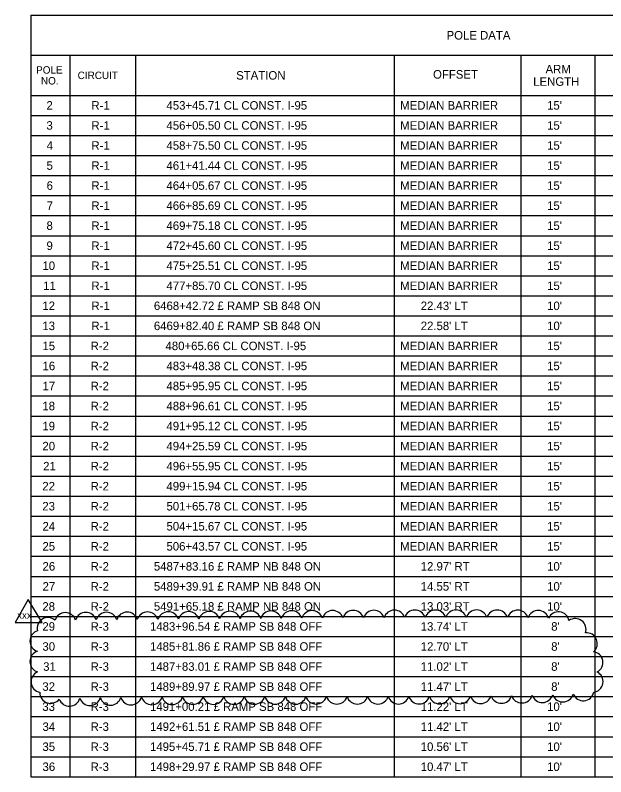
# Model space of a CAD drawing. Extents: x -816.7 to -800.7, y -2197.9 to -2187.9.
# Drawn here: x -816.09 to -811.23, y -2194.13 to -2187.86 of the extents above; entities that cross this region are included whole.
import ezdxf

# ---------------------------------------------------------------- set-up
doc = ezdxf.new("R2010")
doc.units = 0
for name, color, linetype in [('ScratchEle_dp', 7, 'Continuous'), ('SumBoxBorder_dp', 7, 'Continuous'), ('SumBoxLines_dp', 7, 'Continuous'), ('SumBoxLinesMin_dp', 7, 'Continuous'), ('TextLabel', 7, 'Continuous')]:
    doc.layers.add(name, color=color, linetype=linetype)

msp = doc.modelspace()

# ---------------------------------------------------------------- linework, layer by layer
at = {"layer": 'ScratchEle_dp'}
msp.add_lwpolyline([(-815.9867, -2192.6675), (-816.0945, -2192.8556), (-815.8738, -2192.8556)], close=True, dxfattribs=at)
for centre, radius, start, end in [((-815.6819, -2192.8631), 0.0887, 17.94937, 162.94937), ((-815.5126, -2192.8617), 0.0887, 17.94937, 162.94937), ((-815.3433, -2192.8604), 0.0887, 17.94937, 162.94937), ((-815.1741, -2192.8591), 0.0887, 17.94937, 162.94937), ((-815.0048, -2192.8577), 0.0887, 17.94937, 162.94937), ((-814.8355, -2192.8564), 0.0887, 17.94937, 162.94937), ((-814.6663, -2192.8551), 0.0887, 17.94937, 162.94937), ((-814.497, -2192.8538), 0.0887, 17.94937, 162.94937), ((-814.3277, -2192.8524), 0.0887, 17.94937, 162.94937), ((-814.1585, -2192.8511), 0.0887, 17.94937, 162.94937), ((-813.9892, -2192.8498), 0.0887, 17.94937, 162.94937), ((-813.8199, -2192.8485), 0.0887, 17.94104, 162.94104), ((-813.6507, -2192.8472), 0.0887, 17.91499, 162.91499), ((-813.4814, -2192.846), 0.0887, 17.8851, 162.8851), ((-813.3122, -2192.8449), 0.0887, 17.8509, 162.8509), ((-813.1429, -2192.844), 0.0887, 17.81126, 162.81126), ((-812.9737, -2192.8431), 0.0887, 17.76456, 162.76456), ((-812.8044, -2192.8424), 0.0887, 17.70842, 162.70842), ((-812.6352, -2192.8419), 0.0887, 17.63916, 162.63916), ((-812.4659, -2192.8416), 0.0887, 17.55068, 162.55068), ((-812.2967, -2192.8416), 0.0887, 17.43203, 162.43203), ((-812.1275, -2192.8421), 0.0887, 17.26077, 162.26077), ((-811.9584, -2192.8432), 0.0887, 16.98047, 161.98047), ((-811.7894, -2192.8456), 0.0887, 16.37548, 161.37548), ((-811.6233, -2192.8569), 0.0887, 10.88611, 155.88611), ((-815.8256, -2192.9035), 0.0887, 48.4646, 193.4646), ((-811.4843, -2192.9121), 0.0887, 340.74412, 125.74412), ((-815.8852, -2193.0088), 0.0887, 107.5, 252.5), ((-811.3917, -2193.0297), 0.0887, 310.70221, 95.70221), ((-815.8852, -2193.178), 0.0887, 107.5, 252.5), ((-811.3452, -2193.185), 0.0887, 297.61139, 82.61139), ((-815.8756, -2193.3437), 0.0887, 114.144, 259.144), ((-811.3444, -2193.3426), 0.0887, 277.92335, 62.92335), ((-815.8036, -2193.4334), 0.0887, 178.34348, 323.34348), ((-811.4189, -2193.4112), 0.0888, 202.48791, 347.48791), ((-815.6489, -2193.4564), 0.0887, 199.71315, 344.71315), ((-815.4792, -2193.4513), 0.0887, 198.75276, 343.75276), ((-815.3098, -2193.4482), 0.0887, 198.36843, 343.36843), ((-815.1404, -2193.4459), 0.0887, 198.14491, 343.14491), ((-814.9711, -2193.4442), 0.0887, 197.99402, 342.99402), ((-814.8018, -2193.4429), 0.0887, 197.8833, 342.8833), ((-814.6325, -2193.4419), 0.0887, 197.79757, 342.79757), ((-814.4632, -2193.4412), 0.0887, 197.72865, 342.72865), ((-814.2939, -2193.4406), 0.0887, 197.67166, 342.67166), ((-814.1246, -2193.4401), 0.0887, 197.62352, 342.62352), ((-813.9553, -2193.4398), 0.0887, 197.58216, 342.58216), ((-813.786, -2193.4396), 0.0887, 197.5461, 342.5461), ((-813.6167, -2193.4395), 0.0887, 197.51433, 342.51433), ((-813.4474, -2193.4395), 0.0887, 197.52177, 342.52177), ((-813.2782, -2193.4394), 0.0887, 197.56792, 342.56792), ((-813.1089, -2193.4391), 0.0887, 197.6205, 342.6205), ((-812.9397, -2193.4386), 0.0887, 197.68115, 342.68115), ((-812.7704, -2193.438), 0.0887, 197.75216, 342.75216), ((-812.6012, -2193.4371), 0.0887, 197.83689, 342.83689), ((-812.432, -2193.436), 0.0887, 197.94041, 342.94041), ((-812.2628, -2193.4345), 0.0887, 198.07089, 343.07089), ((-812.0936, -2193.4325), 0.0887, 198.24258, 343.24258), ((-811.9244, -2193.43), 0.0887, 198.48321, 343.48321), ((-811.7554, -2193.4265), 0.0887, 198.85675, 343.85675), ((-811.5865, -2193.4215), 0.0887, 199.56532, 344.56532)]:
    msp.add_arc(centre, radius, start, end, dxfattribs=at)
at = {"layer": 'SumBoxBorder_dp'}
for p, q in [((-815.9673, -2187.8562), (-808.5423, -2187.8562)), ((-815.9673, -2187.8562), (-815.9673, -2194.1262)), ((-815.9673, -2188.1862), (-808.5423, -2188.1862)), ((-815.9673, -2188.1862), (-808.5423, -2188.1862)), ((-815.9673, -2194.1262), (-808.5423, -2194.1262))]:
    msp.add_line(p, q, dxfattribs=at)
at = {"layer": 'SumBoxLines_dp'}
for p, q in [((-815.6448, -2188.1862), (-815.6448, -2194.1262)), ((-815.6448, -2188.1862), (-815.6448, -2194.1262)), ((-815.1048, -2188.1862), (-815.1048, -2194.1262)), ((-815.1048, -2188.1862), (-815.1048, -2194.1262)), ((-812.9748, -2188.1862), (-812.9748, -2194.1262)), ((-812.9748, -2188.1862), (-812.9748, -2194.1262)), ((-811.9323, -2188.1862), (-811.9323, -2194.1262)), ((-811.9323, -2188.1862), (-811.9323, -2194.1262)), ((-811.3248, -2188.1862), (-811.3248, -2194.1262)), ((-811.3248, -2188.1862), (-811.3248, -2194.1262)), ((-815.9673, -2188.5162), (-808.5423, -2188.5162))]:
    msp.add_line(p, q, dxfattribs=at)
at = {"layer": 'SumBoxLinesMin_dp'}
for p, q in [((-815.9673, -2188.5162), (-808.5423, -2188.5162)), ((-815.9673, -2188.6812), (-808.5423, -2188.6812)), ((-815.9673, -2188.6812), (-808.5423, -2188.6812)), ((-815.9673, -2188.8462), (-808.5423, -2188.8462)), ((-815.9673, -2188.8462), (-808.5423, -2188.8462)), ((-815.9673, -2189.0112), (-808.5423, -2189.0112)), ((-815.9673, -2189.0112), (-808.5423, -2189.0112)), ((-815.9673, -2189.1762), (-808.5423, -2189.1762)), ((-815.9673, -2189.1762), (-808.5423, -2189.1762)), ((-815.9673, -2189.3412), (-808.5423, -2189.3412)), ((-815.9673, -2189.3412), (-808.5423, -2189.3412)), ((-815.9673, -2189.5062), (-808.5423, -2189.5062)), ((-815.9673, -2189.5062), (-808.5423, -2189.5062)), ((-815.9673, -2189.6712), (-808.5423, -2189.6712)), ((-815.9673, -2189.6712), (-808.5423, -2189.6712)), ((-815.9673, -2189.8362), (-808.5423, -2189.8362)), ((-815.9673, -2189.8362), (-808.5423, -2189.8362)), ((-815.9673, -2190.0012), (-808.5423, -2190.0012)), ((-815.9673, -2190.0012), (-808.5423, -2190.0012)), ((-815.9673, -2190.1662), (-808.5423, -2190.1662)), ((-815.9673, -2190.1662), (-808.5423, -2190.1662)), ((-815.9673, -2190.3312), (-808.5423, -2190.3312)), ((-815.9673, -2190.3312), (-808.5423, -2190.3312)), ((-815.9673, -2190.4962), (-808.5423, -2190.4962)), ((-815.9673, -2190.4962), (-808.5423, -2190.4962)), ((-815.9673, -2190.6612), (-808.5423, -2190.6612)), ((-815.9673, -2190.6612), (-808.5423, -2190.6612)), ((-815.9673, -2190.8262), (-808.5423, -2190.8262)), ((-815.9673, -2190.8262), (-808.5423, -2190.8262)), ((-815.9673, -2190.9912), (-808.5423, -2190.9912)), ((-815.9673, -2190.9912), (-808.5423, -2190.9912)), ((-815.9673, -2191.1562), (-808.5423, -2191.1562)), ((-815.9673, -2191.1562), (-808.5423, -2191.1562)), ((-815.9673, -2191.3212), (-808.5423, -2191.3212)), ((-815.9673, -2191.3212), (-808.5423, -2191.3212)), ((-815.9673, -2191.4862), (-808.5423, -2191.4862)), ((-815.9673, -2191.4862), (-808.5423, -2191.4862)), ((-815.9673, -2191.6512), (-808.5423, -2191.6512)), ((-815.9673, -2191.6512), (-808.5423, -2191.6512)), ((-815.9673, -2191.8162), (-808.5423, -2191.8162)), ((-815.9673, -2191.8162), (-808.5423, -2191.8162)), ((-815.9673, -2191.9812), (-808.5423, -2191.9812)), ((-815.9673, -2191.9812), (-808.5423, -2191.9812)), ((-815.9673, -2192.1462), (-808.5423, -2192.1462)), ((-815.9673, -2192.1462), (-808.5423, -2192.1462)), ((-815.9673, -2192.3112), (-808.5423, -2192.3112)), ((-815.9673, -2192.3112), (-808.5423, -2192.3112)), ((-815.9673, -2192.4762), (-809.8248, -2192.4762)), ((-815.9673, -2192.4762), (-808.5423, -2192.4762)), ((-815.9673, -2192.6412), (-808.5423, -2192.6412)), ((-815.9673, -2192.6412), (-808.5423, -2192.6412)), ((-815.9673, -2192.8062), (-808.5423, -2192.8062)), ((-815.9673, -2192.8062), (-808.5423, -2192.8062)), ((-815.9673, -2192.9712), (-808.5423, -2192.9712)), ((-815.9673, -2192.9712), (-808.5423, -2192.9712)), ((-815.9673, -2193.1362), (-808.5423, -2193.1362)), ((-815.9673, -2193.1362), (-808.5423, -2193.1362)), ((-815.9673, -2193.3012), (-808.5423, -2193.3012)), ((-815.9673, -2193.3012), (-808.5423, -2193.3012)), ((-815.9673, -2193.4662), (-808.5423, -2193.4662)), ((-815.9673, -2193.4662), (-808.5423, -2193.4662)), ((-815.9673, -2193.6312), (-808.5423, -2193.6312)), ((-815.9673, -2193.6312), (-808.5423, -2193.6312)), ((-815.9673, -2193.7962), (-808.5423, -2193.7962)), ((-815.9673, -2193.7962), (-808.5423, -2193.7962)), ((-815.9673, -2193.9612), (-808.5423, -2193.9612)), ((-815.9673, -2193.9612), (-808.5423, -2193.9612))]:
    msp.add_line(p, q, dxfattribs=at)

# ---------------------------------------------------------------- texts
at = {"layer": 'ScratchEle_dp'}
msp.add_text('xxx', height=0.05998, rotation=0, dxfattribs=at).set_placement((-816.0789, -2192.8254))
at = {"layer": 'TextLabel'}
for s, height, p in [('POLE DATA', 0.07, (-812.5438, -2188.0562)), ('POLE', 0.06125, (-815.9227, -2188.3372)), ('ARM', 0.07, (-811.7291, -2188.3352)), ('CIRCUIT', 0.06125, (-815.5808, -2188.3818)), ('STATION', 0.07, (-814.2757, -2188.3862)), ('OFFSET', 0.07, (-812.6551, -2188.3782)), ('NO.', 0.06125, (-815.8828, -2188.4265)), ('LENGTH', 0.07, (-811.8305, -2188.4372)), ('2', 0.07, (-815.8375, -2188.6337)), ('R-1', 0.07, (-815.4673, -2188.6337)), ('453+45.71 CL CONST. I-95', 0.07, (-814.8496, -2188.6337)), ('MEDIAN BARRIER', 0.07, (-812.9257, -2188.6337)), ("15'", 0.07, (-811.7165, -2188.6337)), ('3', 0.07, (-815.8375, -2188.7987)), ('R-1', 0.07, (-815.4673, -2188.7987)), ('456+05.50 CL CONST. I-95', 0.07, (-814.8496, -2188.7987)), ('MEDIAN BARRIER', 0.07, (-812.9257, -2188.7987)), ("15'", 0.07, (-811.7165, -2188.7987)), ('4', 0.07, (-815.8361, -2188.9637)), ('R-1', 0.07, (-815.4673, -2188.9637)), ('458+75.50 CL CONST. I-95', 0.07, (-814.8496, -2188.9637)), ('MEDIAN BARRIER', 0.07, (-812.9257, -2188.9637)), ("15'", 0.07, (-811.7165, -2188.9637)), ('5', 0.07, (-815.8366, -2189.1287)), ('R-1', 0.07, (-815.4673, -2189.1287)), ('461+41.44 CL CONST. I-95', 0.07, (-814.8496, -2189.1287)), ('MEDIAN BARRIER', 0.07, (-812.9257, -2189.1287)), ("15'", 0.07, (-811.7165, -2189.1287)), ('6', 0.07, (-815.8361, -2189.2937)), ('R-1', 0.07, (-815.4673, -2189.2937)), ('464+05.67 CL CONST. I-95', 0.07, (-814.8496, -2189.2937)), ('MEDIAN BARRIER', 0.07, (-812.9257, -2189.2937)), ("15'", 0.07, (-811.7165, -2189.2937)), ('7', 0.07, (-815.8355, -2189.4587)), ('R-1', 0.07, (-815.4673, -2189.4587)), ('466+85.69 CL CONST. I-95', 0.07, (-814.8496, -2189.4587)), ('MEDIAN BARRIER', 0.07, (-812.9257, -2189.4587)), ("15'", 0.07, (-811.7165, -2189.4587)), ('8', 0.07, (-815.8373, -2189.6237)), ('R-1', 0.07, (-815.4673, -2189.6237)), ('469+75.18 CL CONST. I-95', 0.07, (-814.8496, -2189.6237)), ('MEDIAN BARRIER', 0.07, (-812.9257, -2189.6237)), ("15'", 0.07, (-811.7165, -2189.6237)), ('9', 0.07, (-815.8371, -2189.7887)), ('R-1', 0.07, (-815.4673, -2189.7887)), ('472+45.60 CL CONST. I-95', 0.07, (-814.8496, -2189.7887)), ('MEDIAN BARRIER', 0.07, (-812.9257, -2189.7887)), ("15'", 0.07, (-811.7165, -2189.7887)), ('10', 0.07, (-815.8708, -2189.9537)), ('R-1', 0.07, (-815.4673, -2189.9537)), ('475+25.51 CL CONST. I-95', 0.07, (-814.8496, -2189.9537)), ('MEDIAN BARRIER', 0.07, (-812.9257, -2189.9537)), ("15'", 0.07, (-811.7165, -2189.9537)), ('477+85.70 CL CONST. I-95', 0.07, (-814.8496, -2190.1187)), ('11', 0.07, (-815.8646, -2190.1187)), ('R-1', 0.07, (-815.4673, -2190.1187)), ('MEDIAN BARRIER', 0.07, (-812.9257, -2190.1187)), ("15'", 0.07, (-811.7165, -2190.1187)), ('12', 0.07, (-815.8714, -2190.2837)), ('R-1', 0.07, (-815.4673, -2190.2837)), ('6468+42.72 £ RAMP SB 848 ON', 0.07, (-814.9532, -2190.2837)), ("22.43' LT", 0.07, (-812.7567, -2190.2837)), ("10'", 0.07, (-811.7165, -2190.2837)), ('13', 0.07, (-815.8714, -2190.4487)), ('R-1', 0.07, (-815.4673, -2190.4487)), ('6469+82.40 £ RAMP SB 848 ON', 0.07, (-814.9532, -2190.4487)), ("22.58' LT", 0.07, (-812.7567, -2190.4487)), ("10'", 0.07, (-811.7165, -2190.4487)), ('15', 0.07, (-815.8705, -2190.6137)), ('R-2', 0.07, (-815.474, -2190.6137)), (' 480+65.66 CL CONST. I-95', 0.07, (-814.8834, -2190.6137)), ('MEDIAN BARRIER', 0.07, (-812.9257, -2190.6137)), ("15'", 0.07, (-811.7165, -2190.6137)), ('16', 0.07, (-815.87, -2190.7787)), ('R-2', 0.07, (-815.474, -2190.7787)), ('483+48.38 CL CONST. I-95', 0.07, (-814.8496, -2190.7787)), ('MEDIAN BARRIER', 0.07, (-812.9257, -2190.7787)), ("15'", 0.07, (-811.7165, -2190.7787)), ('17', 0.07, (-815.8694, -2190.9437)), ('R-2', 0.07, (-815.474, -2190.9437)), ('485+95.95 CL CONST. I-95', 0.07, (-814.8496, -2190.9437)), ('MEDIAN BARRIER', 0.07, (-812.9257, -2190.9437)), ("15'", 0.07, (-811.7165, -2190.9437)), ('18', 0.07, (-815.8711, -2191.1087)), ('R-2', 0.07, (-815.474, -2191.1087)), ('488+96.61 CL CONST. I-95', 0.07, (-814.8496, -2191.1087)), ('MEDIAN BARRIER', 0.07, (-812.9257, -2191.1087)), ("15'", 0.07, (-811.7165, -2191.1087)), ('19', 0.07, (-815.871, -2191.2737)), ('R-2', 0.07, (-815.474, -2191.2737)), ('491+95.12 CL CONST. I-95', 0.07, (-814.8496, -2191.2737)), ('MEDIAN BARRIER', 0.07, (-812.9257, -2191.2737)), ("15'", 0.07, (-811.7165, -2191.2737)), ('20', 0.07, (-815.8708, -2191.4387)), ('R-2', 0.07, (-815.474, -2191.4387)), ('494+25.59 CL CONST. I-95', 0.07, (-814.8496, -2191.4387)), ('MEDIAN BARRIER', 0.07, (-812.9257, -2191.4387)), ("15'", 0.07, (-811.7165, -2191.4387)), ('21', 0.07, (-815.8646, -2191.6037)), ('R-2', 0.07, (-815.474, -2191.6037)), ('496+55.95 CL CONST. I-95', 0.07, (-814.8496, -2191.6037)), ('MEDIAN BARRIER', 0.07, (-812.9257, -2191.6037)), ("15'", 0.07, (-811.7165, -2191.6037)), ('22', 0.07, (-815.8714, -2191.7687)), ('R-2', 0.07, (-815.474, -2191.7687)), ('499+15.94 CL CONST. I-95', 0.07, (-814.8496, -2191.7687)), ('MEDIAN BARRIER', 0.07, (-812.9257, -2191.7687)), ("15'", 0.07, (-811.7165, -2191.7687)), ('23', 0.07, (-815.8714, -2191.9337)), ('R-2', 0.07, (-815.474, -2191.9337)), ('501+65.78 CL CONST. I-95', 0.07, (-814.8496, -2191.9337)), ('MEDIAN BARRIER', 0.07, (-812.9257, -2191.9337)), ("15'", 0.07, (-811.7165, -2191.9337)), ('24', 0.07, (-815.87, -2192.0987)), ('R-2', 0.07, (-815.474, -2192.0987)), ('504+15.67 CL CONST. I-95', 0.07, (-814.8496, -2192.0987)), ('MEDIAN BARRIER', 0.07, (-812.9257, -2192.0987)), ("15'", 0.07, (-811.7165, -2192.0987)), ('25', 0.07, (-815.8705, -2192.2637)), ('R-2', 0.07, (-815.474, -2192.2637)), ('506+43.57 CL CONST. I-95', 0.07, (-814.8496, -2192.2637)), ('MEDIAN BARRIER', 0.07, (-812.9257, -2192.2637)), ("15'", 0.07, (-811.7165, -2192.2637)), ('26', 0.07, (-815.87, -2192.4287)), ('R-2', 0.07, (-815.474, -2192.4287)), ('5487+83.16 £ RAMP NB 848 ON', 0.07, (-814.9532, -2192.4287)), ("12.97' RT", 0.07, (-812.7567, -2192.4287)), ("10'", 0.07, (-811.7165, -2192.4287)), ('27', 0.07, (-815.8694, -2192.5937)), ('R-2', 0.07, (-815.474, -2192.5937)), ('5489+39.91 £ RAMP NB 848 ON', 0.07, (-814.9532, -2192.5937)), ("14.55' RT", 0.07, (-812.7567, -2192.5937)), ("10'", 0.07, (-811.7165, -2192.5937)), ('28', 0.07, (-815.8711, -2192.7587)), ('R-2', 0.07, (-815.474, -2192.7587)), ('5491+65.18 £ RAMP NB 848 ON', 0.07, (-814.9532, -2192.7587)), ("13.03' RT", 0.07, (-812.7567, -2192.7587)), ("10'", 0.07, (-811.7165, -2192.7587)), ('29', 0.07, (-815.871, -2192.9237)), ('R-3', 0.07, (-815.474, -2192.9237)), ('1483+96.54 £ RAMP SB 848 OFF', 0.07, (-814.9852, -2192.9237)), ("13.74' LT", 0.07, (-812.7567, -2192.9237)), ("8'", 0.07, (-811.6827, -2192.9237)), ('30', 0.07, (-815.8708, -2193.0887)), ('R-3', 0.07, (-815.474, -2193.0887)), ('1485+81.86 £ RAMP SB 848 OFF', 0.07, (-814.9852, -2193.0887)), ("12.70' LT", 0.07, (-812.7567, -2193.0887)), ("8'", 0.07, (-811.6827, -2193.0887)), ('31', 0.07, (-815.8646, -2193.2537)), ('R-3', 0.07, (-815.474, -2193.2537)), ('1487+83.01 £ RAMP SB 848 OFF', 0.07, (-814.9852, -2193.2537)), ("11.02' LT", 0.07, (-812.7567, -2193.2537)), ("8'", 0.07, (-811.6827, -2193.2537)), ('32', 0.07, (-815.8714, -2193.4187)), ('R-3', 0.07, (-815.474, -2193.4187)), ('1489+89.97 £ RAMP SB 848 OFF', 0.07, (-814.9852, -2193.4187)), ("11.47' LT", 0.07, (-812.7567, -2193.4187)), ("8'", 0.07, (-811.6827, -2193.4187)), ('33', 0.07, (-815.8714, -2193.5837)), ('R-3', 0.07, (-815.474, -2193.5837)), ('1491+00.21 £ RAMP SB 848 OFF', 0.07, (-814.9852, -2193.5837)), ("11.22' LT", 0.07, (-812.7567, -2193.5837)), ("10'", 0.07, (-811.7165, -2193.5837)), ('34', 0.07, (-815.87, -2193.7487)), ('R-3', 0.07, (-815.474, -2193.7487)), ('1492+61.51 £ RAMP SB 848 OFF', 0.07, (-814.9852, -2193.7487)), ("11.42' LT", 0.07, (-812.7567, -2193.7487)), ("10'", 0.07, (-811.7165, -2193.7487)), ('35', 0.07, (-815.8705, -2193.9137)), ('R-3', 0.07, (-815.474, -2193.9137)), ('1495+45.71 £ RAMP SB 848 OFF', 0.07, (-814.9852, -2193.9137)), ("10.56' LT", 0.07, (-812.7567, -2193.9137)), ("10'", 0.07, (-811.7165, -2193.9137)), ('36', 0.07, (-815.87, -2194.0787)), ('R-3', 0.07, (-815.474, -2194.0787)), ('1498+29.97 £ RAMP SB 848 OFF', 0.07, (-814.9852, -2194.0787)), ("10.47' LT", 0.07, (-812.7567, -2194.0787)), ("10'", 0.07, (-811.7165, -2194.0787))]:
    msp.add_text(s, height=height, dxfattribs=at).set_placement(p)

doc.saveas('drawing.dxf')
